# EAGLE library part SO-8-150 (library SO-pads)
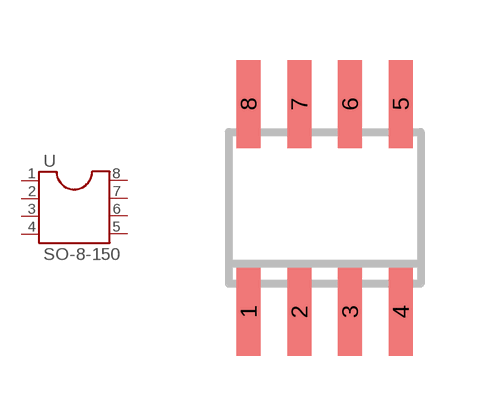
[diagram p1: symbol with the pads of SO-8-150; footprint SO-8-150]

Designator prefix -

## SO-8-150  [SO-8-150]
1  1  pas
2  2  pas
3  3  pas
4  4  pas
5  5  pas
6  6  pas
7  7  pas
8  8  pas

## Footprint SO-8-150 (pad centres in mm)
smd 0.6 x 2.2: 1 -1.905,-2.6; 2 -0.635,-2.6; 3 0.635,-2.6; 4 1.905,-2.6; 5 1.905,2.6; 6 0.635,2.6; 7 -0.635,2.6; 8 -1.905,2.6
